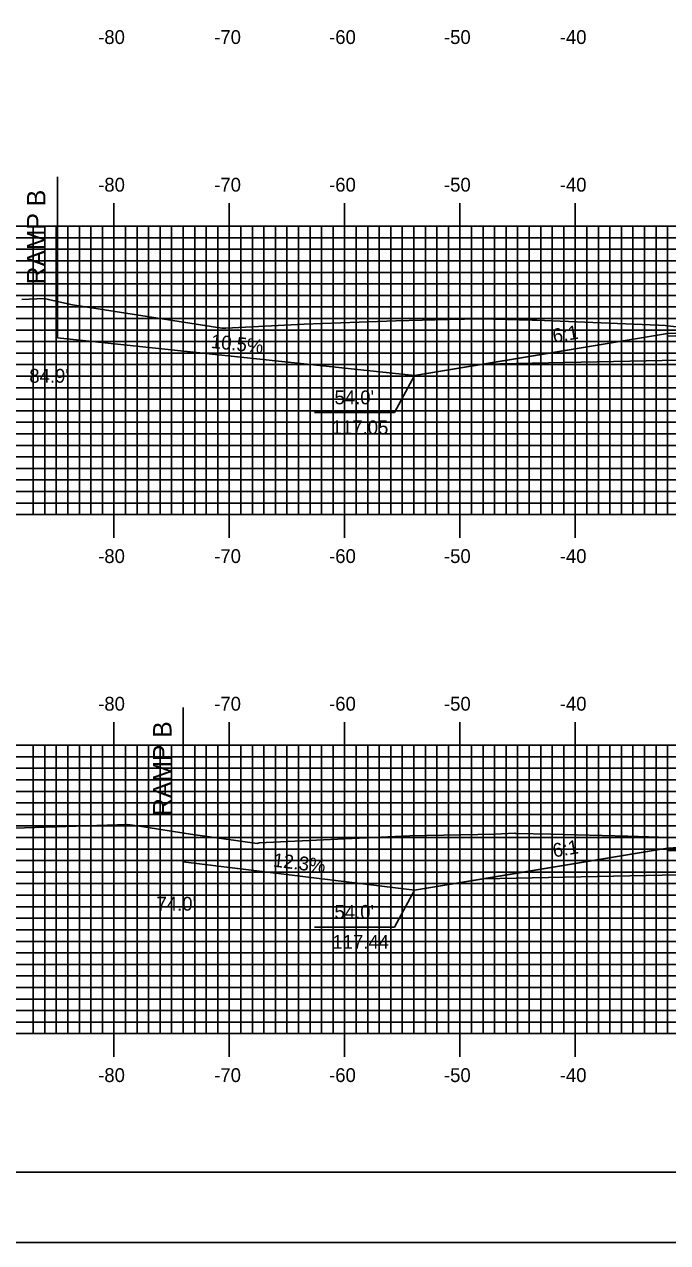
# Model space of a CAD drawing. Extents: x 854287 to 854631, y 366605 to 366825.
# Drawn here: x 854365.3 to 854421, y 366604.9 to 366710.6 of the extents above; entities that cross this region are included whole.
import ezdxf

# ---------------------------------------------------------------- set-up
doc = ezdxf.new("R2010")
doc.units = 0
for name, color, linetype in [('ANNOTATION', 7, 'Continuous'), ('BORDER', 7, 'Continuous'), ('D_Roadway_Centerline', 7, 'Continuous'), ('D_Roadway_SubGrade', 7, 'Continuous'), ('D_Text_Standard', 7, 'Continuous'), ('H_V ANNOTATION', 7, 'Continuous'), ('M_Roadway_Centerline', 7, 'Continuous'), ('MAJOR', 7, 'Continuous'), ('MINOR', 7, 'Continuous'), ('PLOT BOUNDARY', 7, 'Continuous'), ('S_Roadway_Centerline', 7, 'Continuous')]:
    doc.layers.add(name, color=color, linetype=linetype)

msp = doc.modelspace()

# ---------------------------------------------------------------- linework, layer by layer
at = {"layer": 'ANNOTATION'}
for points in [[(854405.09, 366681.11), (854399.09, 366680.11), (854368.14, 366683.37)], [(854390.43, 366676.9), (854397.36, 366676.9), (854399.09, 366680.11)], [(854405.09, 366636.49), (854399.09, 366635.49), (854379.04, 366637.95)], [(854390.43, 366632.28), (854397.36, 366632.28), (854399.09, 366635.49)]]:
    msp.add_lwpolyline(points, dxfattribs=at)
at = {"layer": 'BORDER'}
msp.add_lwpolyline([(854303.44, 366611.06), (854623.44, 366611.06), (854623.44, 366821.06), (854303.44, 366821.06)], close=True, dxfattribs=at)
at = {"layer": 'D_Roadway_Centerline'}
for points in [[(854403.95, 366680.92), (854421.04, 366683.77), (854421.04, 366683.77), (854429.03, 366684.08), (854429.04, 366684.09), (854438.03, 366684.26), (854441.04, 366684.33), (854441.05, 366684.33), (854453.04, 366684.57), (854457.04, 366684.41), (854463.16, 366683.81), (854465.84, 366683.55)], [(854403.95, 366636.3), (854403.96, 366636.3), (854417.85, 366638.62), (854421.04, 366639.15), (854422.54, 366639.21), (854429.04, 366639.47), (854429.04, 366639.47), (854435.92, 366639.61), (854441.04, 366639.71), (854441.05, 366639.71), (854453.04, 366639.95), (854454.91, 366639.88), (854457.04, 366639.79), (854457.05, 366639.79), (854467.03, 366638.84)]]:
    msp.add_lwpolyline(points, dxfattribs=at)
at = {"layer": 'D_Roadway_SubGrade'}
for p, q in [((854368.14, 366697.33), (854368.14, 366683.37)), ((854379.04, 366651.33), (854379.04, 366637.95))]:
    msp.add_line(p, q, dxfattribs=at)
for points in [[(854403.95, 366680.92), (854399.09, 366680.11), (854368.14, 366683.37)], [(854403.95, 366636.3), (854399.09, 366635.49), (854379.04, 366637.95)]]:
    msp.add_lwpolyline(points, dxfattribs=at)
for points in [[(854429.04, 366683.42), (854429.04, 366683.42), (854429.04, 366683.84), (854421.04, 366683.52), (854421.04, 366683.77), (854405.09, 366681.11), (854429.04, 366681.59)], [(854429.04, 366638.8), (854429.04, 366638.8), (854429.04, 366639.22), (854421.04, 366638.9), (854421.04, 366639.15), (854405.09, 366636.49), (854429.04, 366636.97)]]:
    msp.add_lwpolyline(points, close=True, dxfattribs=at)
at = {"layer": 'MAJOR'}
for p, q in [((854373.04, 366695.06), (854373.04, 366693.06)), ((854383.04, 366695.06), (854383.04, 366693.06)), ((854393.04, 366695.06), (854393.04, 366693.06)), ((854403.04, 366695.06), (854403.04, 366693.06)), ((854413.04, 366695.06), (854413.04, 366693.06)), ((854313.04, 366693.06), (854593.04, 366693.06)), ((854313.04, 366693.06), (854593.04, 366693.06)), ((854373.04, 366668.06), (854373.04, 366693.06)), ((854383.04, 366668.06), (854383.04, 366693.06)), ((854393.04, 366668.06), (854393.04, 366693.06)), ((854403.04, 366668.06), (854403.04, 366693.06)), ((854413.04, 366668.06), (854413.04, 366693.06)), ((854313.04, 366688.06), (854593.04, 366688.06)), ((854313.04, 366683.06), (854593.04, 366683.06)), ((854313.04, 366678.06), (854593.04, 366678.06)), ((854313.04, 366673.06), (854593.04, 366673.06)), ((854313.04, 366668.06), (854593.04, 366668.06)), ((854313.04, 366668.06), (854593.04, 366668.06)), ((854373.04, 366666.05), (854373.04, 366668.06)), ((854383.04, 366666.05), (854383.04, 366668.06)), ((854393.04, 366666.05), (854393.04, 366668.06)), ((854403.04, 366666.05), (854403.04, 366668.06)), ((854413.04, 366666.05), (854413.04, 366668.06)), ((854373.04, 366650.06), (854373.04, 366648.06)), ((854383.04, 366650.06), (854383.04, 366648.06)), ((854393.04, 366650.06), (854393.04, 366648.06)), ((854403.04, 366650.06), (854403.04, 366648.06)), ((854413.04, 366650.06), (854413.04, 366648.06)), ((854313.04, 366648.06), (854593.04, 366648.06)), ((854313.04, 366648.06), (854593.04, 366648.06)), ((854373.04, 366623.06), (854373.04, 366648.06)), ((854383.04, 366623.06), (854383.04, 366648.06)), ((854393.04, 366623.06), (854393.04, 366648.06)), ((854403.04, 366623.06), (854403.04, 366648.06)), ((854413.04, 366623.06), (854413.04, 366648.06)), ((854313.04, 366643.06), (854593.04, 366643.06)), ((854313.04, 366638.06), (854593.04, 366638.06)), ((854313.04, 366633.06), (854593.04, 366633.06)), ((854313.04, 366628.06), (854593.04, 366628.06)), ((854313.04, 366623.06), (854593.04, 366623.06)), ((854313.04, 366623.06), (854593.04, 366623.06)), ((854373.04, 366621.05), (854373.04, 366623.06)), ((854383.04, 366621.05), (854383.04, 366623.06)), ((854393.04, 366621.05), (854393.04, 366623.06)), ((854403.04, 366621.05), (854403.04, 366623.06)), ((854413.04, 366621.05), (854413.04, 366623.06))]:
    msp.add_line(p, q, dxfattribs=at)
at = {"layer": 'MINOR'}
for p, q in [((854366.04, 366668.06), (854366.04, 366693.06)), ((854367.04, 366668.06), (854367.04, 366693.06)), ((854368.04, 366668.06), (854368.04, 366693.06)), ((854369.04, 366668.06), (854369.04, 366693.06)), ((854370.04, 366668.06), (854370.04, 366693.06)), ((854371.04, 366668.06), (854371.04, 366693.06)), ((854372.04, 366668.06), (854372.04, 366693.06)), ((854374.04, 366668.06), (854374.04, 366693.06)), ((854375.04, 366668.06), (854375.04, 366693.06)), ((854376.04, 366668.06), (854376.04, 366693.06)), ((854377.04, 366668.06), (854377.04, 366693.06)), ((854378.04, 366668.06), (854378.04, 366693.06)), ((854379.04, 366668.06), (854379.04, 366693.06)), ((854380.04, 366668.06), (854380.04, 366693.06)), ((854381.04, 366668.06), (854381.04, 366693.06)), ((854382.04, 366668.06), (854382.04, 366693.06)), ((854384.04, 366668.06), (854384.04, 366693.06)), ((854385.04, 366668.06), (854385.04, 366693.06)), ((854386.04, 366668.06), (854386.04, 366693.06)), ((854387.04, 366668.06), (854387.04, 366693.06)), ((854388.04, 366668.06), (854388.04, 366693.06)), ((854389.04, 366668.06), (854389.04, 366693.06)), ((854390.04, 366668.06), (854390.04, 366693.06)), ((854391.04, 366668.06), (854391.04, 366693.06)), ((854392.04, 366668.06), (854392.04, 366693.06)), ((854394.04, 366668.06), (854394.04, 366693.06)), ((854395.04, 366668.06), (854395.04, 366693.06)), ((854396.04, 366668.06), (854396.04, 366693.06)), ((854397.04, 366668.06), (854397.04, 366693.06)), ((854398.04, 366668.06), (854398.04, 366693.06)), ((854399.04, 366668.06), (854399.04, 366693.06)), ((854400.04, 366668.06), (854400.04, 366693.06)), ((854401.04, 366668.06), (854401.04, 366693.06)), ((854402.04, 366668.06), (854402.04, 366693.06)), ((854404.04, 366668.06), (854404.04, 366693.06)), ((854405.04, 366668.06), (854405.04, 366693.06)), ((854406.04, 366668.06), (854406.04, 366693.06)), ((854407.04, 366668.06), (854407.04, 366693.06)), ((854408.04, 366668.06), (854408.04, 366693.06)), ((854409.04, 366668.06), (854409.04, 366693.06)), ((854410.04, 366668.06), (854410.04, 366693.06)), ((854411.04, 366668.06), (854411.04, 366693.06)), ((854412.04, 366668.06), (854412.04, 366693.06)), ((854414.04, 366668.06), (854414.04, 366693.06)), ((854415.04, 366668.06), (854415.04, 366693.06)), ((854416.04, 366668.06), (854416.04, 366693.06)), ((854417.04, 366668.06), (854417.04, 366693.06)), ((854418.04, 366668.06), (854418.04, 366693.06)), ((854419.04, 366668.06), (854419.04, 366693.06)), ((854420.04, 366668.06), (854420.04, 366693.06)), ((854421.04, 366668.06), (854421.04, 366693.06)), ((854313.04, 366692.06), (854593.04, 366692.06)), ((854313.04, 366691.06), (854593.04, 366691.06)), ((854313.04, 366690.06), (854593.04, 366690.06)), ((854313.04, 366689.06), (854593.04, 366689.06)), ((854313.04, 366687.06), (854593.04, 366687.06)), ((854313.04, 366686.06), (854593.04, 366686.06)), ((854313.04, 366685.06), (854593.04, 366685.06)), ((854313.04, 366684.06), (854593.04, 366684.06)), ((854313.04, 366682.06), (854593.04, 366682.06)), ((854313.04, 366681.06), (854593.04, 366681.06)), ((854313.04, 366680.06), (854593.04, 366680.06)), ((854313.04, 366679.06), (854593.04, 366679.06)), ((854313.04, 366677.06), (854593.04, 366677.06)), ((854313.04, 366676.06), (854593.04, 366676.06)), ((854313.04, 366675.06), (854593.04, 366675.06)), ((854313.04, 366674.06), (854593.04, 366674.06)), ((854313.04, 366672.06), (854593.04, 366672.06)), ((854313.04, 366671.06), (854593.04, 366671.06)), ((854313.04, 366670.06), (854593.04, 366670.06)), ((854313.04, 366669.06), (854593.04, 366669.06)), ((854366.04, 366623.06), (854366.04, 366648.06)), ((854367.04, 366623.06), (854367.04, 366648.06)), ((854368.04, 366623.06), (854368.04, 366648.06)), ((854369.04, 366623.06), (854369.04, 366648.06)), ((854370.04, 366623.06), (854370.04, 366648.06)), ((854371.04, 366623.06), (854371.04, 366648.06)), ((854372.04, 366623.06), (854372.04, 366648.06)), ((854374.04, 366623.06), (854374.04, 366648.06)), ((854375.04, 366623.06), (854375.04, 366648.06)), ((854376.04, 366623.06), (854376.04, 366648.06)), ((854377.04, 366623.06), (854377.04, 366648.06)), ((854378.04, 366623.06), (854378.04, 366648.06)), ((854379.04, 366623.06), (854379.04, 366648.06)), ((854380.04, 366623.06), (854380.04, 366648.06)), ((854381.04, 366623.06), (854381.04, 366648.06)), ((854382.04, 366623.06), (854382.04, 366648.06)), ((854384.04, 366623.06), (854384.04, 366648.06)), ((854385.04, 366623.06), (854385.04, 366648.06)), ((854386.04, 366623.06), (854386.04, 366648.06)), ((854387.04, 366623.06), (854387.04, 366648.06)), ((854388.04, 366623.06), (854388.04, 366648.06)), ((854389.04, 366623.06), (854389.04, 366648.06)), ((854390.04, 366623.06), (854390.04, 366648.06)), ((854391.04, 366623.06), (854391.04, 366648.06)), ((854392.04, 366623.06), (854392.04, 366648.06)), ((854394.04, 366623.06), (854394.04, 366648.06)), ((854395.04, 366623.06), (854395.04, 366648.06)), ((854396.04, 366623.06), (854396.04, 366648.06)), ((854397.04, 366623.06), (854397.04, 366648.06)), ((854398.04, 366623.06), (854398.04, 366648.06)), ((854399.04, 366623.06), (854399.04, 366648.06)), ((854400.04, 366623.06), (854400.04, 366648.06)), ((854401.04, 366623.06), (854401.04, 366648.06)), ((854402.04, 366623.06), (854402.04, 366648.06)), ((854404.04, 366623.06), (854404.04, 366648.06)), ((854405.04, 366623.06), (854405.04, 366648.06)), ((854406.04, 366623.06), (854406.04, 366648.06)), ((854407.04, 366623.06), (854407.04, 366648.06)), ((854408.04, 366623.06), (854408.04, 366648.06)), ((854409.04, 366623.06), (854409.04, 366648.06)), ((854410.04, 366623.06), (854410.04, 366648.06)), ((854411.04, 366623.06), (854411.04, 366648.06)), ((854412.04, 366623.06), (854412.04, 366648.06)), ((854414.04, 366623.06), (854414.04, 366648.06)), ((854415.04, 366623.06), (854415.04, 366648.06)), ((854416.04, 366623.06), (854416.04, 366648.06)), ((854417.04, 366623.06), (854417.04, 366648.06)), ((854418.04, 366623.06), (854418.04, 366648.06)), ((854419.04, 366623.06), (854419.04, 366648.06)), ((854420.04, 366623.06), (854420.04, 366648.06)), ((854421.04, 366623.06), (854421.04, 366648.06)), ((854313.04, 366647.06), (854593.04, 366647.06)), ((854313.04, 366646.06), (854593.04, 366646.06)), ((854313.04, 366645.06), (854593.04, 366645.06)), ((854313.04, 366644.06), (854593.04, 366644.06)), ((854313.04, 366642.06), (854593.04, 366642.06)), ((854313.04, 366641.06), (854593.04, 366641.06)), ((854313.04, 366640.06), (854593.04, 366640.06)), ((854313.04, 366639.06), (854593.04, 366639.06)), ((854313.04, 366637.06), (854593.04, 366637.06)), ((854313.04, 366636.06), (854593.04, 366636.06)), ((854313.04, 366635.06), (854593.04, 366635.06)), ((854313.04, 366634.06), (854593.04, 366634.06)), ((854313.04, 366632.06), (854593.04, 366632.06)), ((854313.04, 366631.06), (854593.04, 366631.06)), ((854313.04, 366630.06), (854593.04, 366630.06)), ((854313.04, 366629.06), (854593.04, 366629.06)), ((854313.04, 366627.06), (854593.04, 366627.06)), ((854313.04, 366626.06), (854593.04, 366626.06)), ((854313.04, 366625.06), (854593.04, 366625.06)), ((854313.04, 366624.06), (854593.04, 366624.06))]:
    msp.add_line(p, q, dxfattribs=at)
at = {"layer": 'PLOT BOUNDARY'}
msp.add_lwpolyline([(854287.26, 366604.94), (854627.26, 366604.94), (854627.26, 366824.94), (854287.26, 366824.94)], close=True, dxfattribs=at)
at = {"layer": 'S_Roadway_Centerline'}
for points in [[(854365.05, 366686.71), (854366.98, 366686.79), (854367.73, 366686.63), (854369.45, 366686.25), (854382.38, 366684.21), (854382.43, 366684.21), (854382.43, 366684.21), (854382.74, 366684.22), (854389.53, 366684.56), (854397.47, 366684.85), (854402.03, 366684.96), (854404.81, 366685.04), (854409.29, 366684.93), (854409.3, 366684.93), (854409.69, 366684.92), (854411.74, 366684.82), (854420.25, 366684.49), (854420.83, 366684.45), (854425.61, 366683.87)], [(854362.11, 366640.81), (854365.29, 366640.89), (854374.25, 366641.18), (854375.25, 366641.05), (854379.68, 366640.36), (854385.45, 366639.55), (854385.63, 366639.6), (854398.03, 366640.18), (854398.32, 366640.19), (854398.69, 366640.21), (854406.07, 366640.36), (854407.79, 366640.43), (854407.87, 366640.4), (854410.92, 366640.34), (854417.59, 366640.17), (854422.07, 366640.02)]]:
    msp.add_lwpolyline(points, dxfattribs=at)

# ---------------------------------------------------------------- texts
at = {"layer": 'ANNOTATION'}
for s, height, rotation, p in [('RAMP B', 1.6, 90, (854367.1, 366688.02)), ('6:1', 1.2, 9.4604, (854411.17, 366682.95)), ('10.5%', 1.2, 353.9826, (854381.4, 366682.51)), ("54.0' ", 1.2, 360, (854392.16, 366677.62)), ('117.05', 1.2, 360, (854391.92, 366675.02)), ('RAMP B', 1.6, 90, (854378.03, 366641.93)), ('6:1', 1.2, 9.4609, (854411.18, 366638.33)), ('12.3%', 1.2, 353.0107, (854386.79, 366637.54)), ("54.0' ", 1.2, 360, (854392.16, 366633.01)), ('117.44', 1.2, 360, (854391.98, 366630.41))]:
    msp.add_text(s, height=height, rotation=rotation, dxfattribs=at).set_placement(p)
at = {"layer": 'D_Text_Standard'}
for s, p in [("84.9'", (854365.7, 366679.49)), ("74.0'", (854376.73, 366633.72))]:
    msp.add_text(s, height=1.2, dxfattribs=at).set_placement(p)
at = {"layer": 'H_V ANNOTATION'}
for s, p in [('-80', (854371.67, 366708.86)), ('-70', (854381.73, 366708.86)), ('-60', (854391.69, 366708.86)), ('-50', (854401.65, 366708.86)), ('-40', (854411.69, 366708.86)), ('-80', (854371.67, 366696.06)), ('-70', (854381.73, 366696.06)), ('-60', (854391.69, 366696.06)), ('-50', (854401.65, 366696.06)), ('-40', (854411.69, 366696.06)), ('-80', (854371.67, 366663.86)), ('-70', (854381.73, 366663.86)), ('-60', (854391.69, 366663.86)), ('-50', (854401.65, 366663.86)), ('-40', (854411.69, 366663.86)), ('-80', (854371.67, 366651.06)), ('-70', (854381.73, 366651.06)), ('-60', (854391.69, 366651.06)), ('-50', (854401.65, 366651.06)), ('-40', (854411.69, 366651.06)), ('-80', (854371.67, 366618.86)), ('-70', (854381.73, 366618.86)), ('-60', (854391.69, 366618.86)), ('-50', (854401.65, 366618.86)), ('-40', (854411.69, 366618.86))]:
    msp.add_text(s, height=1.2, dxfattribs=at).set_placement(p)
at = {"layer": 'M_Roadway_Centerline'}
for s, p in [('C', (854404.8, 366685.04)), ('L', (854404.81, 366685.04)), ('C', (854407.79, 366640.43)), ('L', (854407.79, 366640.42))]:
    msp.add_text(s, height=0.0146, dxfattribs=at).set_placement(p)

doc.saveas('drawing.dxf')
